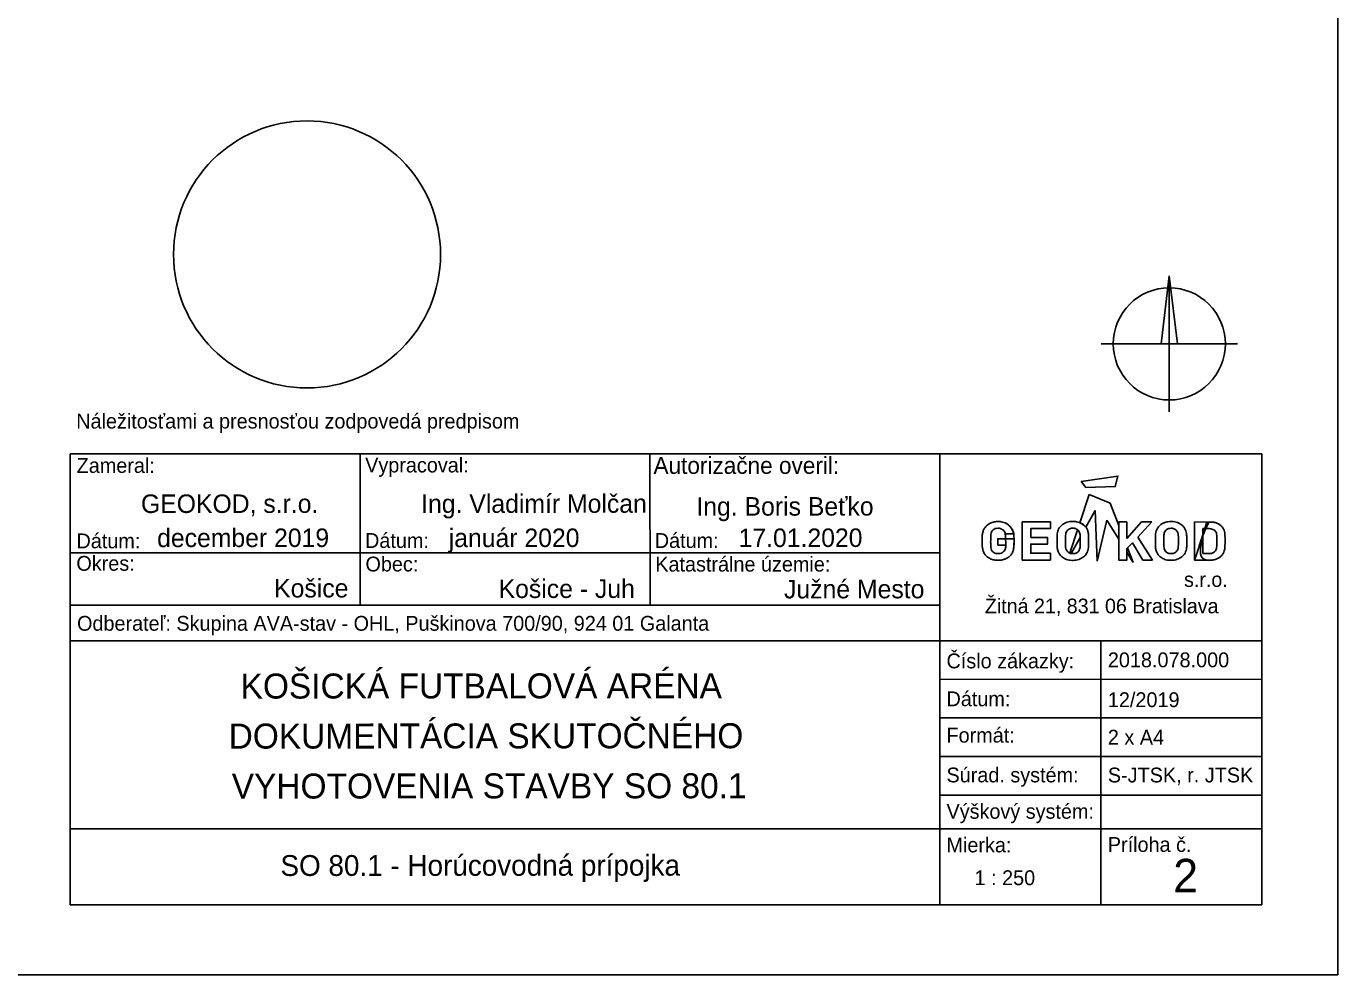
# Model space of a CAD drawing. Extents: x -263964 to -263859, y -1242287 to -1242158.
# Drawn here: x -263910.6 to -263859.3, y -1242232 to -1242194.9 of the extents above; entities that cross this region are included whole.
import ezdxf

# ---------------------------------------------------------------- set-up
doc = ezdxf.new("R2010")
doc.units = 0
doc.layers.add('RAM_NA_TLAC_A3_1-250', color=7, linetype='Continuous')
doc.layers.add('ROZPISKA', color=7, linetype='Continuous')

msp = doc.modelspace()

# ---------------------------------------------------------------- linework, layer by layer
at = {"layer": 'RAM_NA_TLAC_A3_1-250'}
msp.add_lwpolyline([(-263964.307, -1242157.773), (-263859.307, -1242157.773), (-263859.307, -1242232.023), (-263964.307, -1242232.023)], close=True, dxfattribs=at)
at = {"layer": 'ROZPISKA'}
for p, q in [((-263865.899, -1242204.667), (-263866.215, -1242207.332)), ((-263865.899, -1242204.667), (-263865.899, -1242209.997)), ((-263865.899, -1242204.667), (-263865.583, -1242207.331)), ((-263868.564, -1242207.332), (-263863.234, -1242207.331)), ((-263908.908, -1242211.637), (-263908.909, -1242229.284)), ((-263908.908, -1242211.637), (-263862.275, -1242211.637)), ((-263897.567, -1242211.636), (-263897.563, -1242217.564)), ((-263886.224, -1242211.639), (-263886.22, -1242217.561)), ((-263874.877, -1242218.695), (-263874.879, -1242211.636)), ((-263862.275, -1242211.637), (-263862.274, -1242229.284)), ((-263869.398, -1242214.332), (-263869.032, -1242213.225)), ((-263869.032, -1242213.225), (-263868.219, -1242213.57)), ((-263868.8, -1242213.854), (-263869.164, -1242214.507)), ((-263868.728, -1242215.829), (-263868.8, -1242213.854)), ((-263868.219, -1242213.57), (-263867.876, -1242214.443)), ((-263869.695, -1242214.279), (-263869.669, -1242214.278)), ((-263868.338, -1242214.229), (-263868.728, -1242215.829)), ((-263867.876, -1242214.973), (-263868.338, -1242214.229)), ((-263867.558, -1242214.298), (-263867.876, -1242214.298)), ((-263867.876, -1242214.443), (-263867.876, -1242214.973)), ((-263866.982, -1242214.298), (-263867.558, -1242214.951)), ((-263867.558, -1242214.951), (-263867.558, -1242214.298)), ((-263867.134, -1242214.899), (-263866.585, -1242214.298)), ((-263866.585, -1242214.298), (-263866.982, -1242214.298)), ((-263864.908, -1242214.302), (-263864.432, -1242214.303)), ((-263864.908, -1242215.792), (-263864.908, -1242214.302)), ((-263864.908, -1242214.302), (-263864.908, -1242215.792)), ((-263864.432, -1242214.303), (-263864.908, -1242214.302)), ((-263871.98, -1242214.761), (-263872.311, -1242214.761)), ((-263872.311, -1242214.761), (-263871.98, -1242214.761)), ((-263869.488, -1242214.606), (-263869.792, -1242215.526)), ((-263869.689, -1242214.546), (-263869.672, -1242214.545)), ((-263869.689, -1242214.546), (-263869.672, -1242214.545)), ((-263866.556, -1242215.792), (-263867.134, -1242214.899)), ((-263864.582, -1242214.561), (-263864.582, -1242215.533)), ((-263864.582, -1242214.561), (-263864.582, -1242215.533)), ((-263867.308, -1242215.887), (-263867.558, -1242215.485)), ((-263867.532, -1242215.318), (-263867.308, -1242215.887)), ((-263908.911, -1242215.51), (-263874.878, -1242215.51)), ((-263866.932, -1242215.792), (-263866.556, -1242215.792)), ((-263908.909, -1242217.561), (-263874.879, -1242217.561)), ((-263908.912, -1242218.951), (-263874.875, -1242218.947)), ((-263874.877, -1242218.695), (-263874.878, -1242223.235)), ((-263874.875, -1242218.947), (-263862.273, -1242218.947)), ((-263868.577, -1242218.949), (-263868.576, -1242223.487)), ((-263874.878, -1242220.46), (-263862.275, -1242220.463)), ((-263874.88, -1242221.973), (-263862.273, -1242221.972)), ((-263874.88, -1242223.485), (-263862.272, -1242223.487)), ((-263874.878, -1242223.235), (-263874.878, -1242229.282)), ((-263868.576, -1242223.487), (-263868.574, -1242229.283)), ((-263874.878, -1242224.999), (-263862.273, -1242224.997)), ((-263908.91, -1242226.309), (-263862.273, -1242226.307)), ((-263908.909, -1242229.284), (-263862.274, -1242229.284))]:
    msp.add_line(p, q, dxfattribs=at)
for points in [[(-263865.899, -1242204.667), (-263865.583, -1242207.331), (-263865.899, -1242207.331)], [(-263869.355, -1242212.711), (-263867.911, -1242212.503), (-263868.012, -1242212.915), (-263869.163, -1242212.952)], [(-263871.652, -1242214.291), (-263871.652, -1242215.792), (-263870.553, -1242215.792), (-263870.553, -1242215.527), (-263871.322, -1242215.527), (-263871.322, -1242215.168), (-263870.664, -1242215.168), (-263870.664, -1242214.907), (-263871.322, -1242214.907), (-263871.322, -1242214.557), (-263870.553, -1242214.557), (-263870.553, -1242214.291)]]:
    msp.add_lwpolyline(points, close=True, dxfattribs=at)
for points in [[(-263869.164, -1242214.507), (-263869.174, -1242214.493), (-263869.193, -1242214.472), (-263869.212, -1242214.453), (-263869.234, -1242214.434), (-263869.256, -1242214.416), (-263869.28, -1242214.398), (-263869.301, -1242214.385), (-263869.324, -1242214.371), (-263869.35, -1242214.355), (-263869.373, -1242214.342), (-263869.398, -1242214.332)], [(-263867.876, -1242214.298), (-263867.876, -1242215.792), (-263867.558, -1242215.792), (-263867.558, -1242215.346), (-263867.346, -1242215.121), (-263866.932, -1242215.792)], [(-263872.3, -1242215.203), (-263872.612, -1242215.203), (-263872.612, -1242214.955), (-263871.976, -1242214.955)], [(-263871.976, -1242214.955), (-263872.612, -1242214.955), (-263872.612, -1242215.203), (-263872.3, -1242215.203)], [(-263869.74, -1242215.54), (-263869.389, -1242214.911)], [(-263869.389, -1242214.911), (-263869.39, -1242214.878), (-263869.391, -1242214.837), (-263869.394, -1242214.8), (-263869.4, -1242214.763), (-263869.409, -1242214.73), (-263869.422, -1242214.693), (-263869.442, -1242214.658), (-263869.464, -1242214.629), (-263869.488, -1242214.606)], [(-263867.558, -1242215.485), (-263867.558, -1242215.346), (-263867.532, -1242215.318)], [(-263869.792, -1242215.526), (-263869.783, -1242215.529), (-263869.774, -1242215.532), (-263869.765, -1242215.535), (-263869.755, -1242215.537), (-263869.747, -1242215.539), (-263869.74, -1242215.54)]]:
    msp.add_lwpolyline(points, dxfattribs=at)
for centre, radius in [((-263899.644, -1242203.828), 5.225), ((-263865.899, -1242207.332), 2.194)]:
    msp.add_circle(centre, radius, dxfattribs=at)
for points in [[(-263871.976, -1242214.955), (-263871.975, -1242215.144), (-263871.98, -1242215.314), (-263872.014, -1242215.465), (-263872.086, -1242215.586), (-263872.198, -1242215.688), (-263872.315, -1242215.756), (-263872.47, -1242215.795), (-263872.611, -1242215.805), (-263872.757, -1242215.795), (-263872.903, -1242215.747), (-263873.029, -1242215.664), (-263873.126, -1242215.567), (-263873.189, -1242215.436), (-263873.218, -1242215.29), (-263873.223, -1242215.193), (-263873.223, -1242214.897), (-263873.213, -1242214.736), (-263873.17, -1242214.6), (-263873.097, -1242214.484), (-263872.951, -1242214.367), (-263872.796, -1242214.299), (-263872.616, -1242214.28), (-263872.427, -1242214.294), (-263872.227, -1242214.377), (-263872.072, -1242214.523), (-263871.98, -1242214.761), (-263871.976, -1242214.955), (-263871.98, -1242214.761)], [(-263871.98, -1242214.761), (-263872.072, -1242214.523), (-263872.227, -1242214.377), (-263872.427, -1242214.294), (-263872.616, -1242214.28), (-263872.796, -1242214.299), (-263872.951, -1242214.367), (-263873.097, -1242214.484), (-263873.17, -1242214.6), (-263873.213, -1242214.736), (-263873.223, -1242214.897), (-263873.223, -1242215.193), (-263873.218, -1242215.29), (-263873.189, -1242215.436), (-263873.126, -1242215.567), (-263873.029, -1242215.664), (-263872.903, -1242215.747), (-263872.757, -1242215.795), (-263872.611, -1242215.805), (-263872.47, -1242215.795), (-263872.315, -1242215.756), (-263872.198, -1242215.688), (-263872.086, -1242215.586), (-263872.014, -1242215.465), (-263871.98, -1242215.314), (-263871.975, -1242215.144), (-263871.976, -1242214.955), (-263871.98, -1242214.761), (-263871.976, -1242214.955)], [(-263869.669, -1242214.278), (-263869.661, -1242214.278), (-263869.616, -1242214.277), (-263869.532, -1242214.298), (-263869.42, -1242214.317), (-263869.313, -1242214.375), (-263869.217, -1242214.442), (-263869.137, -1242214.535), (-263869.091, -1242214.64), (-263869.062, -1242214.755), (-263869.063, -1242214.936), (-263869.058, -1242215.122), (-263869.062, -1242215.305), (-263869.079, -1242215.421), (-263869.122, -1242215.517), (-263869.177, -1242215.602), (-263869.252, -1242215.668), (-263869.334, -1242215.727), (-263869.434, -1242215.767), (-263869.544, -1242215.799), (-263869.663, -1242215.807), (-263869.775, -1242215.8), (-263869.874, -1242215.791), (-263869.96, -1242215.752), (-263870.04, -1242215.705), (-263870.118, -1242215.655), (-263870.187, -1242215.582), (-263870.243, -1242215.485), (-263870.283, -1242215.366), (-263870.299, -1242215.171), (-263870.283, -1242214.989), (-263870.292, -1242214.814), (-263870.276, -1242214.714), (-263870.255, -1242214.617), (-263870.206, -1242214.53), (-263870.143, -1242214.459), (-263870.076, -1242214.395), (-263869.99, -1242214.349), (-263869.893, -1242214.306), (-263869.791, -1242214.285), (-263869.723, -1242214.281), (-263869.695, -1242214.279)], [(-263865.824, -1242214.278), (-263865.934, -1242214.286), (-263866.052, -1242214.312), (-263866.149, -1242214.352), (-263866.228, -1242214.399), (-263866.298, -1242214.46), (-263866.356, -1242214.529), (-263866.405, -1242214.619), (-263866.431, -1242214.716), (-263866.444, -1242214.811), (-263866.443, -1242214.916), (-263866.447, -1242215.238), (-263866.434, -1242215.359), (-263866.39, -1242215.492), (-263866.334, -1242215.587), (-263866.275, -1242215.648), (-263866.191, -1242215.707), (-263866.114, -1242215.751), (-263866.032, -1242215.784), (-263865.932, -1242215.799), (-263865.825, -1242215.804), (-263865.696, -1242215.794), (-263865.584, -1242215.763), (-263865.494, -1242215.725), (-263865.405, -1242215.663), (-263865.335, -1242215.599), (-263865.282, -1242215.52), (-263865.238, -1242215.418), (-263865.22, -1242215.313), (-263865.215, -1242215.182), (-263865.218, -1242214.872), (-263865.223, -1242214.752), (-263865.248, -1242214.644), (-263865.3, -1242214.534), (-263865.369, -1242214.452), (-263865.476, -1242214.373), (-263865.574, -1242214.324), (-263865.689, -1242214.296), (-263865.801, -1242214.278), (-263865.824, -1242214.278), (-263865.824, -1242214.278), (-263865.824, -1242214.278)], [(-263864.432, -1242214.303), (-263864.275, -1242214.303), (-263864.179, -1242214.308), (-263864.108, -1242214.322), (-263864.015, -1242214.354), (-263863.927, -1242214.404), (-263863.838, -1242214.486), (-263863.773, -1242214.581), (-263863.741, -1242214.669), (-263863.72, -1242214.806), (-263863.719, -1242214.874), (-263863.718, -1242215.171), (-263863.722, -1242215.268), (-263863.729, -1242215.347), (-263863.743, -1242215.432), (-263863.786, -1242215.536), (-263863.86, -1242215.632), (-263863.97, -1242215.719), (-263864.06, -1242215.758), (-263864.151, -1242215.784), (-263864.227, -1242215.792), (-263864.254, -1242215.792), (-263864.908, -1242215.792), (-263864.432, -1242214.303), (-263864.908, -1242215.792)], [(-263864.908, -1242215.792), (-263864.254, -1242215.792), (-263864.227, -1242215.792), (-263864.151, -1242215.784), (-263864.06, -1242215.758), (-263863.97, -1242215.719), (-263863.86, -1242215.632), (-263863.786, -1242215.536), (-263863.743, -1242215.432), (-263863.729, -1242215.347), (-263863.722, -1242215.268), (-263863.718, -1242215.171), (-263863.719, -1242214.874), (-263863.72, -1242214.806), (-263863.741, -1242214.669), (-263863.773, -1242214.581), (-263863.838, -1242214.486), (-263863.927, -1242214.404), (-263864.015, -1242214.354), (-263864.108, -1242214.322), (-263864.179, -1242214.308), (-263864.275, -1242214.303), (-263864.432, -1242214.303), (-263864.908, -1242215.792), (-263864.432, -1242214.303)], [(-263872.308, -1242214.761), (-263872.34, -1242214.679), (-263872.413, -1242214.599), (-263872.512, -1242214.552), (-263872.612, -1242214.545), (-263872.712, -1242214.557), (-263872.792, -1242214.603), (-263872.85, -1242214.667), (-263872.879, -1242214.735), (-263872.882, -1242214.837), (-263872.889, -1242214.948), (-263872.891, -1242215.082), (-263872.889, -1242215.24), (-263872.877, -1242215.356), (-263872.833, -1242215.449), (-263872.77, -1242215.502), (-263872.695, -1242215.534), (-263872.614, -1242215.543), (-263872.52, -1242215.538), (-263872.42, -1242215.497), (-263872.35, -1242215.429), (-263872.308, -1242215.351), (-263872.299, -1242215.262), (-263872.3, -1242215.203), (-263872.308, -1242214.761), (-263872.3, -1242215.203)], [(-263872.3, -1242215.203), (-263872.299, -1242215.262), (-263872.308, -1242215.351), (-263872.35, -1242215.429), (-263872.42, -1242215.497), (-263872.52, -1242215.538), (-263872.614, -1242215.543), (-263872.695, -1242215.534), (-263872.77, -1242215.502), (-263872.833, -1242215.449), (-263872.877, -1242215.356), (-263872.889, -1242215.24), (-263872.891, -1242215.082), (-263872.889, -1242214.948), (-263872.882, -1242214.837), (-263872.879, -1242214.735), (-263872.85, -1242214.667), (-263872.792, -1242214.603), (-263872.712, -1242214.557), (-263872.612, -1242214.545), (-263872.512, -1242214.552), (-263872.413, -1242214.599), (-263872.34, -1242214.679), (-263872.308, -1242214.761), (-263872.3, -1242215.203), (-263872.308, -1242214.761)], [(-263869.672, -1242214.545), (-263869.658, -1242214.546), (-263869.624, -1242214.546), (-263869.564, -1242214.559), (-263869.498, -1242214.594), (-263869.439, -1242214.651), (-263869.402, -1242214.735), (-263869.387, -1242214.826), (-263869.39, -1242214.928), (-263869.387, -1242215.034), (-263869.391, -1242215.144), (-263869.385, -1242215.245), (-263869.4, -1242215.331), (-263869.42, -1242215.408), (-263869.468, -1242215.476), (-263869.54, -1242215.523), (-263869.616, -1242215.544), (-263869.678, -1242215.54), (-263869.734, -1242215.543), (-263869.795, -1242215.529), (-263869.854, -1242215.492), (-263869.91, -1242215.437), (-263869.95, -1242215.356), (-263869.963, -1242215.259), (-263869.958, -1242215.14), (-263869.961, -1242215.009), (-263869.958, -1242214.883), (-263869.955, -1242214.779), (-263869.938, -1242214.698), (-263869.894, -1242214.632), (-263869.832, -1242214.581), (-263869.761, -1242214.55), (-263869.711, -1242214.546), (-263869.689, -1242214.546)], [(-263869.672, -1242214.545), (-263869.658, -1242214.546), (-263869.624, -1242214.546), (-263869.564, -1242214.559), (-263869.498, -1242214.594), (-263869.439, -1242214.651), (-263869.402, -1242214.735), (-263869.387, -1242214.826), (-263869.39, -1242214.928), (-263869.387, -1242215.034), (-263869.391, -1242215.144), (-263869.385, -1242215.245), (-263869.4, -1242215.331), (-263869.42, -1242215.408), (-263869.468, -1242215.476), (-263869.54, -1242215.523), (-263869.616, -1242215.544), (-263869.678, -1242215.54), (-263869.734, -1242215.543), (-263869.795, -1242215.529), (-263869.854, -1242215.492), (-263869.91, -1242215.437), (-263869.95, -1242215.356), (-263869.963, -1242215.259), (-263869.958, -1242215.14), (-263869.961, -1242215.009), (-263869.958, -1242214.883), (-263869.955, -1242214.779), (-263869.938, -1242214.698), (-263869.894, -1242214.632), (-263869.832, -1242214.581), (-263869.761, -1242214.55), (-263869.711, -1242214.546), (-263869.689, -1242214.546)], [(-263865.827, -1242214.545), (-263865.908, -1242214.552), (-263865.987, -1242214.586), (-263866.048, -1242214.637), (-263866.087, -1242214.696), (-263866.107, -1242214.778), (-263866.112, -1242214.867), (-263866.115, -1242215.003), (-263866.115, -1242215.157), (-263866.115, -1242215.262), (-263866.1, -1242215.356), (-263866.059, -1242215.438), (-263866.005, -1242215.492), (-263865.948, -1242215.525), (-263865.884, -1242215.541), (-263865.833, -1242215.541), (-263865.782, -1242215.541), (-263865.7, -1242215.52), (-263865.621, -1242215.466), (-263865.58, -1242215.408), (-263865.557, -1242215.333), (-263865.544, -1242215.249), (-263865.544, -1242215.152), (-263865.543, -1242215.031), (-263865.544, -1242214.921), (-263865.545, -1242214.833), (-263865.564, -1242214.726), (-263865.598, -1242214.655), (-263865.657, -1242214.596), (-263865.726, -1242214.56), (-263865.785, -1242214.547), (-263865.827, -1242214.545), (-263865.827, -1242214.545), (-263865.827, -1242214.545)], [(-263864.582, -1242215.533), (-263864.487, -1242215.534), (-263864.387, -1242215.534), (-263864.283, -1242215.533), (-263864.265, -1242215.534), (-263864.227, -1242215.525), (-263864.167, -1242215.495), (-263864.091, -1242215.442), (-263864.054, -1242215.349), (-263864.043, -1242215.25), (-263864.045, -1242215.109), (-263864.043, -1242214.95), (-263864.045, -1242214.82), (-263864.052, -1242214.732), (-263864.087, -1242214.671), (-263864.153, -1242214.609), (-263864.227, -1242214.575), (-263864.329, -1242214.561), (-263864.398, -1242214.56), (-263864.539, -1242214.562), (-263864.582, -1242214.561)], [(-263864.582, -1242215.533), (-263864.487, -1242215.534), (-263864.387, -1242215.534), (-263864.283, -1242215.533), (-263864.265, -1242215.534), (-263864.227, -1242215.525), (-263864.167, -1242215.495), (-263864.091, -1242215.442), (-263864.054, -1242215.349), (-263864.043, -1242215.25), (-263864.045, -1242215.109), (-263864.043, -1242214.95), (-263864.045, -1242214.82), (-263864.052, -1242214.732), (-263864.087, -1242214.671), (-263864.153, -1242214.609), (-263864.227, -1242214.575), (-263864.329, -1242214.561), (-263864.398, -1242214.56), (-263864.539, -1242214.562), (-263864.582, -1242214.561)]]:
    msp.add_open_spline(points, degree=3, dxfattribs=at)

# ---------------------------------------------------------------- texts
for s, height, rotation, p in [('Náležitosťami a presnosťou zodpovedá predpisom', 0.57967, 0.0016, (-263908.676, -1242210.644)), ('Zameral:', 0.5796, 0.0016, (-263908.658, -1242212.38)), ('Vypracoval:', 0.57967, 0.0016, (-263897.368, -1242212.363)), ('Autorizačne overil:', 0.66068, 0.0016, (-263886.086, -1242212.419)), ('GEOKOD, s.r.o.', 0.7244, 0.0456, (-263906.143, -1242213.95)), ('Ing. Vladimír Molčan', 0.72454, 0.0456, (-263895.177, -1242213.948)), ('Ing. Boris Beťko', 0.7249, 0.0456, (-263884.408, -1242214.056)), ('Dátum:', 0.5797, 0.0016, (-263908.665, -1242215.332)), ('december 2019', 0.7244, 0.0456, (-263905.51, -1242215.286)), ('Dátum:', 0.5797, 0.0016, (-263897.373, -1242215.316)), ('január 2020', 0.7244, 0.0456, (-263894.098, -1242215.286)), ('Dátum:', 0.5797, 0.0016, (-263886.035, -1242215.317)), ('17.01.2020', 0.7244, 0.0456, (-263882.754, -1242215.283)), ('Okres:', 0.5797, 0.0016, (-263908.669, -1242216.211)), ('Obec:', 0.5797, 0.0016, (-263897.357, -1242216.238)), ('Katastrálne územie:', 0.57967, 0.0016, (-263886.015, -1242216.241)), ('Košice', 0.7247, 0.0456, (-263900.931, -1242217.257)), ('Košice - Juh', 0.7249, 0.0456, (-263892.147, -1242217.278)), ('Južné Mesto', 0.7249, 0.0456, (-263880.978, -1242217.293)), ('s.r.o.', 0.5748, 0.0016, (-263865.322, -1242216.842)), ('Žitná 21, 831 06 Bratislava', 0.57475, 0.0016, (-263873.117, -1242217.877)), ('Odberateľ: Skupina AVA-stav - OHL, Puškinova 700/90, 924 01 Galanta', 0.57952, 0.0016, (-263908.643, -1242218.559)), ('Číslo zákazky:', 0.57952, 0.0016, (-263874.618, -1242220.03)), ('KOŠICKÁ FUTBALOVÁ ARÉNA', 0.97862, 0.0456, (-263902.242, -1242221.214)), ('Dátum:', 0.5797, 0.0016, (-263874.618, -1242221.513)), ('DOKUMENTÁCIA SKUTOČNÉHO', 0.97862, 0.0456, (-263902.71, -1242223.172)), ('Formát:', 0.5797, 0.0016, (-263874.618, -1242222.937)), ('VYHOTOVENIA STAVBY SO 80.1', 0.97862, 0.0456, (-263902.589, -1242225.129)), ('Súrad. systém:', 0.57952, 0.0016, (-263874.618, -1242224.493)), ('Výškový systém:', 0.57951, 0.0016, (-263874.618, -1242225.917)), ('Mierka:', 0.5797, 0.0016, (-263874.618, -1242227.233)), ('Príloha č.', 0.5795, 0.0016, (-263868.305, -1242227.215)), ('SO 80.1 - Horúcovodná prípojka', 0.81531, 0.0456, (-263900.683, -1242228.156))]:
    msp.add_text(s, height=height, rotation=rotation, dxfattribs=at).set_placement(p)
for s, height, p in [('2018.078.000', 0.5805, (-263868.305, -1242219.988)), ('12/2019', 0.5805, (-263868.305, -1242221.549)), ('2 x A4', 0.5805, (-263868.305, -1242223.014)), ('S-JTSK, r. JTSK', 0.5805, (-263868.305, -1242224.496)), ('2', 1.306, (-263865.745, -1242228.792)), ('1 : 250', 0.5805, (-263873.523, -1242228.516))]:
    msp.add_text(s, height=height, dxfattribs=at).set_placement(p)

doc.saveas('drawing.dxf')
